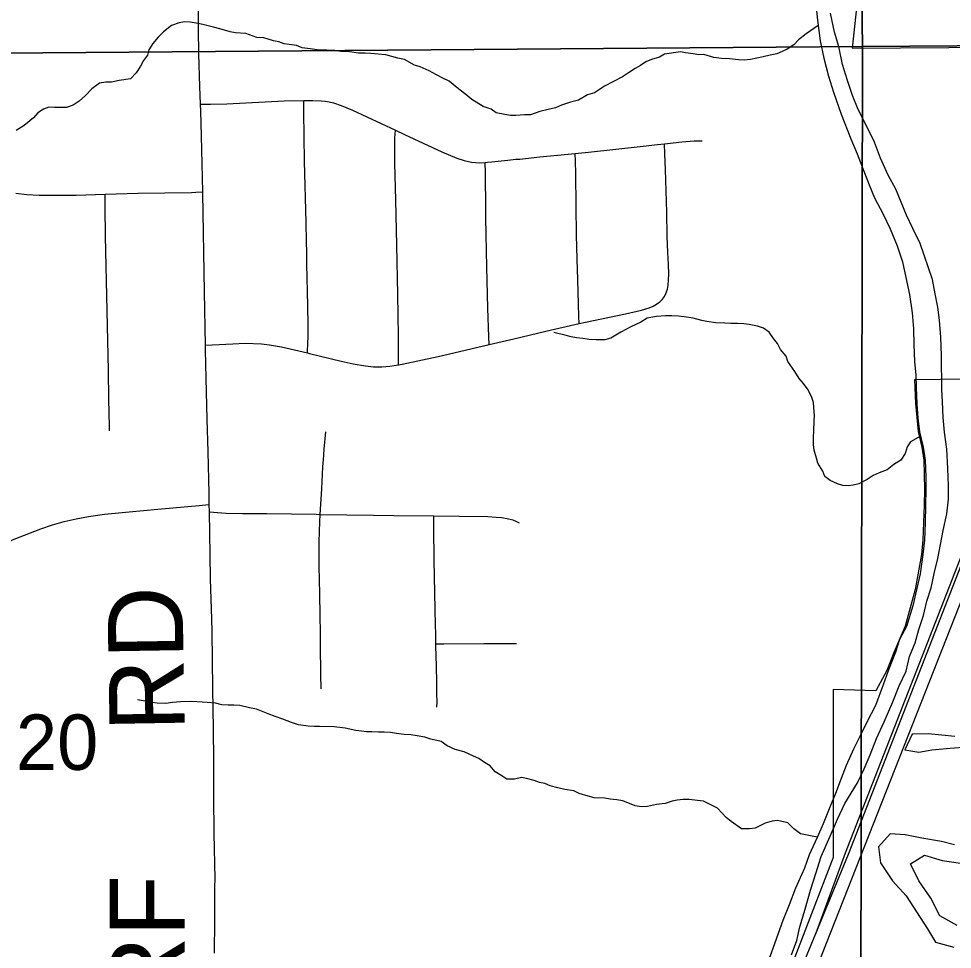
# Model space of a CAD drawing. Extents: x 0 to 34, y 0 to 22.
# Drawn here: x 7.158 to 7.864, y 18.2 to 18.904 of the extents above; entities that cross this region are included whole.
import ezdxf

# ---------------------------------------------------------------- set-up
doc = ezdxf.new("R2010")
doc.units = 0
for name, color, linetype in [('Default', 7, 'Continuous'), ('GM_X_Major_River', 7, 'Continuous'), ('GM_X_Minor_River', 7, 'Continuous'), ('GM_X_Rail_Line', 7, 'Continuous'), ('GM_X_Section', 7, 'Continuous'), ('GM_X_Section_Text', 7, 'Continuous'), ('GM_X_Township_Road', 7, 'Continuous'), ('GM_X_Township_Road_Text', 7, 'Continuous')]:
    doc.layers.add(name, color=color, linetype=linetype)

msp = doc.modelspace()

# ---------------------------------------------------------------- linework, layer by layer
at = {"layer": 'Default'}
for points in [[(7.81905, 19.16934), (7.78812, 18.88167), (7.97091, 18.88297)], [(7.87401, 18.63157), (7.83533, 18.63091), (7.83607, 18.61316), (7.83811, 18.59194), (7.84085, 18.5802), (7.84242, 18.57035), (7.84296, 18.54836), (7.84266, 18.53623), (7.84171, 18.51005), (7.84065, 18.49905), (7.83591, 18.47246), (7.82815, 18.44472), (7.81995, 18.42531), (7.81436, 18.41124), (7.80613, 18.39581), (7.77387, 18.39692), (7.77385, 18.26998), (7.71339, 18.11258)]]:
    msp.add_lwpolyline(points, dxfattribs=at)
at = {"layer": 'GM_X_Major_River'}
for points in [[(7.76077, 18.91468), (7.76199, 18.90293), (7.76399, 18.8874), (7.76673, 18.87415), (7.77024, 18.86052), (7.77411, 18.84841), (7.7799, 18.83177), (7.78723, 18.81324), (7.79185, 18.8019), (7.79571, 18.79207), (7.8011, 18.77846), (7.80496, 18.76862), (7.81148, 18.75616), (7.81686, 18.7452), (7.82225, 18.73235), (7.82612, 18.72024), (7.82885, 18.7085), (7.83159, 18.69563), (7.83358, 18.68161), (7.83442, 18.66948), (7.83488, 18.65773), (7.83535, 18.64484), (7.83618, 18.63461), (7.83662, 18.62513), (7.83709, 18.613), (7.83792, 18.602), (7.83913, 18.59178), (7.84186, 18.58004), (7.84344, 18.57019), (7.84391, 18.55768), (7.84397, 18.5482), (7.84368, 18.53606), (7.84339, 18.52316), (7.84272, 18.50989), (7.84166, 18.49888), (7.83949, 18.48445), (7.83692, 18.4723), (7.83398, 18.46014), (7.82916, 18.44455), (7.82392, 18.43465), (7.82096, 18.42515), (7.81538, 18.41107)], [(7.85685, 18.60253), (7.85639, 18.61428), (7.85595, 18.62376), (7.85577, 18.64954), (7.8553, 18.6632), (7.85407, 18.67608), (7.85287, 18.68593), (7.8509, 18.69615), (7.84894, 18.70676), (7.83966, 18.734), (7.8339, 18.74533), (7.82928, 18.75553), (7.8212, 18.77519), (7.81544, 18.78577), (7.80967, 18.79862), (7.80504, 18.81072), (7.79928, 18.82243), (7.79275, 18.83528), (7.78852, 18.84587), (7.78465, 18.85722), (7.78078, 18.86932), (7.77803, 18.88295), (7.77493, 18.89393), (7.7718, 18.90832)], [(7.74225, 18.19625), (7.74634, 18.20728), (7.74854, 18.21754), (7.75262, 18.23084), (7.75668, 18.24528), (7.76076, 18.25783), (7.76484, 18.27075), (7.77155, 18.28598), (7.77714, 18.29891), (7.78274, 18.31071), (7.7921, 18.32633), (7.79733, 18.33699), (7.8018, 18.34764), (7.80664, 18.35981), (7.81224, 18.37237), (7.81895, 18.38759), (7.82379, 18.39976), (7.82901, 18.4108), (7.83159, 18.42182), (7.83568, 18.43209), (7.83864, 18.44235), (7.84198, 18.45299), (7.84455, 18.46363), (7.84789, 18.47389), (7.85009, 18.48453), (7.85304, 18.49593), (7.85486, 18.50656), (7.85706, 18.5172), (7.85963, 18.52973), (7.86107, 18.54074), (7.86099, 18.55098), (7.86053, 18.56387), (7.85967, 18.57866), (7.85807, 18.59154), (7.85685, 18.60253)], [(7.81538, 18.41107), (7.81166, 18.40043), (7.80571, 18.38483), (7.79936, 18.37227), (7.79413, 18.36199), (7.78928, 18.35172), (7.78368, 18.33954), (7.77996, 18.32965), (7.77549, 18.31824), (7.7714, 18.30797), (7.76618, 18.29542), (7.76171, 18.28514), (7.75574, 18.27182), (7.75202, 18.26193), (7.74531, 18.24671), (7.74047, 18.23416), (7.73563, 18.22237), (7.73229, 18.21248), (7.7282, 18.20108), (7.72449, 18.19081)]]:
    msp.add_lwpolyline(points, dxfattribs=at)
at = {"layer": 'GM_X_Minor_River'}
for points in [[(7.7625, 18.89898), (7.75335, 18.8927), (7.7477, 18.88807), (7.74395, 18.88422), (7.73904, 18.88111), (7.73527, 18.87917), (7.7311, 18.87759), (7.72617, 18.87638), (7.72087, 18.87518), (7.71138, 18.87315), (7.70645, 18.8727), (7.70226, 18.87303), (7.6954, 18.87369), (7.68931, 18.87399), (7.6836, 18.87468), (7.67597, 18.87686), (7.67216, 18.8768), (7.66797, 18.87751), (7.66226, 18.87819), (7.65844, 18.8789), (7.6463, 18.87722), (7.64252, 18.87489), (7.63646, 18.87329), (7.6323, 18.87133), (7.62815, 18.86862), (7.624, 18.86628), (7.6191, 18.86318), (7.61457, 18.86008), (7.60097, 18.85306), (7.59343, 18.84803), (7.58813, 18.84643), (7.58133, 18.84254), (7.57527, 18.84095), (7.56845, 18.83857), (7.56391, 18.83661), (7.55822, 18.8354), (7.55216, 18.8338), (7.54496, 18.83143), (7.5404, 18.83136), (7.53394, 18.8309), (7.52976, 18.83084), (7.52557, 18.83155), (7.51908, 18.83298), (7.51524, 18.83559), (7.50913, 18.83778), (7.5007, 18.84299), (7.49608, 18.84673), (7.49185, 18.85009), (7.48801, 18.85308), (7.4834, 18.85681), (7.47881, 18.85903), (7.47383, 18.86162), (7.46847, 18.86459), (7.46158, 18.86754), (7.45738, 18.869), (7.44972, 18.87308), (7.44476, 18.87415), (7.4356, 18.87669), (7.42418, 18.87768), (7.41999, 18.878), (7.41505, 18.87793), (7.40819, 18.87898), (7.40172, 18.87928), (7.39715, 18.87998), (7.39106, 18.88027), (7.38383, 18.88056), (7.37849, 18.88125), (7.3724, 18.88193), (7.36819, 18.88377), (7.36248, 18.88445), (7.35867, 18.88516), (7.35484, 18.88663), (7.35065, 18.88733), (7.3434, 18.88951), (7.33807, 18.88982), (7.32967, 18.89275), (7.32205, 18.89341), (7.31786, 18.89411), (7.31022, 18.89629), (7.30526, 18.89774), (7.29725, 18.89953), (7.29229, 18.90061), (7.28772, 18.90131), (7.28353, 18.90163), (7.27936, 18.90082), (7.27368, 18.89884), (7.26765, 18.8942), (7.26352, 18.88997), (7.2594, 18.88535), (7.25642, 18.88038), (7.25533, 18.87656), (7.25234, 18.87235), (7.25012, 18.86814), (7.24676, 18.86315), (7.24263, 18.85854), (7.2339, 18.85728), (7.22821, 18.85607), (7.22403, 18.85601), (7.2191, 18.85519)], [(7.2191, 18.85519), (7.21345, 18.85093), (7.20857, 18.84593), (7.20368, 18.84169), (7.19916, 18.83859), (7.19423, 18.837), (7.18511, 18.83688), (7.18092, 18.83721), (7.17676, 18.83563), (7.17261, 18.83292), (7.16924, 18.82907), (7.16209, 18.82328), (7.15605, 18.8194)], [(7.83991, 18.58839), (7.83228, 18.58417), (7.82967, 18.58033), (7.82821, 18.57538), (7.82485, 18.57039), (7.81957, 18.5669), (7.81468, 18.56304), (7.80862, 18.56068), (7.80408, 18.55872), (7.79956, 18.55562), (7.79314, 18.5525), (7.78897, 18.5513), (7.78517, 18.55087), (7.78098, 18.55119), (7.77717, 18.55228), (7.77142, 18.55487), (7.76758, 18.55786), (7.76601, 18.56201), (7.76213, 18.56804), (7.76132, 18.57182), (7.75934, 18.57788), (7.7589, 18.58205), (7.75883, 18.58775), (7.75915, 18.59231), (7.75943, 18.59991), (7.75976, 18.60371), (7.7593, 18.61016), (7.75887, 18.61396), (7.75768, 18.61774), (7.75494, 18.6234), (7.75146, 18.62829), (7.74798, 18.63204), (7.74487, 18.63732), (7.73945, 18.64485), (7.73826, 18.64901), (7.73401, 18.65389), (7.73167, 18.65842), (7.72858, 18.66218), (7.72547, 18.66707), (7.72125, 18.67005), (7.71667, 18.67151), (7.71018, 18.67295), (7.70637, 18.67328), (7.70143, 18.67359), (7.69648, 18.67352), (7.69191, 18.67384), (7.68507, 18.67413), (7.67821, 18.67518), (7.67439, 18.67589), (7.6679, 18.6777), (7.66104, 18.67875), (7.65685, 18.67907), (7.65191, 18.67939), (7.64696, 18.67932), (7.64012, 18.67885), (7.63329, 18.67762), (7.62839, 18.67451), (7.62083, 18.671), (7.61328, 18.6671), (7.60573, 18.66244), (7.60118, 18.66124), (7.59471, 18.66115), (7.58939, 18.66146), (7.58443, 18.66215), (7.57986, 18.66285), (7.57567, 18.66356), (7.57185, 18.66464), (7.5627, 18.6668)], [(7.76182, 18.28538), (7.74903, 18.28791), (7.74404, 18.29164), (7.73942, 18.29614), (7.73179, 18.29793), (7.72761, 18.2975), (7.7223, 18.29591), (7.71475, 18.29201), (7.71057, 18.29157), (7.70449, 18.29149), (7.69681, 18.29709), (7.69297, 18.30007), (7.68641, 18.30721), (7.67569, 18.31238), (7.66464, 18.31375), (7.66046, 18.3137), (7.6559, 18.31326), (7.65211, 18.31245), (7.64681, 18.31086), (7.64035, 18.31001), (7.63353, 18.3084), (7.62896, 18.30834), (7.62401, 18.30903), (7.61483, 18.31271), (7.61026, 18.31341), (7.60531, 18.3141), (7.60112, 18.3148), (7.59313, 18.31508), (7.58855, 18.31616), (7.58167, 18.31834), (7.57785, 18.32019), (7.57099, 18.32124), (7.56564, 18.32269), (7.55992, 18.32413), (7.55571, 18.32597), (7.5519, 18.32668), (7.5477, 18.32815), (7.54197, 18.32959), (7.53816, 18.3303), (7.53285, 18.32909), (7.52715, 18.32901), (7.52331, 18.33162), (7.51833, 18.33459), (7.51447, 18.3391), (7.51025, 18.3417), (7.50603, 18.34468), (7.50182, 18.34653), (7.49493, 18.34985), (7.48806, 18.35166), (7.48194, 18.35424), (7.47734, 18.3576), (7.46971, 18.35939), (7.46512, 18.36085), (7.45941, 18.36192), (7.45445, 18.36261), (7.4495, 18.36292), (7.44379, 18.36361), (7.43922, 18.36431), (7.43427, 18.36462), (7.43009, 18.36457), (7.42514, 18.36488), (7.42096, 18.36482), (7.41714, 18.36553), (7.41296, 18.36586), (7.40495, 18.36765), (7.39657, 18.36868), (7.38553, 18.36891), (7.38135, 18.36885), (7.37678, 18.36917), (7.36954, 18.37021), (7.36419, 18.37204), (7.3577, 18.37461), (7.35197, 18.37644), (7.34661, 18.37864), (7.34164, 18.38048), (7.33782, 18.38195), (7.33249, 18.38301), (7.32524, 18.38482), (7.32067, 18.38514), (7.31649, 18.38508), (7.31153, 18.38539), (7.30696, 18.38647), (7.30048, 18.38714), (7.29668, 18.38747), (7.28907, 18.38775), (7.28032, 18.38764), (7.27424, 18.38718), (7.26931, 18.38635), (7.26284, 18.38664), (7.25598, 18.38769), (7.25217, 18.3884), (7.24797, 18.38911)], [(7.86571, 18.36139), (7.85586, 18.36246), (7.84563, 18.36352), (7.83351, 18.36305), (7.82791, 18.35125), (7.83853, 18.34943), (7.84836, 18.3514), (7.86236, 18.35265), (7.87561, 18.3535)], [(7.86552, 18.27948), (7.85565, 18.28206), (7.84087, 18.2846), (7.82835, 18.28716), (7.81699, 18.28783), (7.80796, 18.2779), (7.80956, 18.26578), (7.81874, 18.2522), (7.82905, 18.2409), (7.84513, 18.21599), (7.85126, 18.2058), (7.86492, 18.20211)], [(7.86746, 18.21843), (7.85453, 18.22592), (7.84762, 18.23914), (7.83844, 18.25235), (7.83229, 18.26519), (7.84285, 18.27172), (7.85613, 18.26765), (7.87547, 18.26476)]]:
    msp.add_lwpolyline(points, dxfattribs=at)
at = {"layer": 'GM_X_Rail_Line'}
for points in [[(7.41554, 16.97974), (7.45576, 17.1778), (7.51777, 17.49987), (7.54259, 17.62251), (7.57169, 17.70433), (7.63213, 17.85839), (7.88249, 18.49369), (8.02356, 18.85844), (8.15149, 19.17223), (8.16753, 19.23137), (8.32815, 19.89453)], [(7.19563, 16.97974), (7.27479, 17.11509), (7.3911, 17.31365), (7.42821, 17.37942), (7.44573, 17.41447), (7.46435, 17.45781), (7.63148, 17.88537), (7.72591, 18.12796), (7.78531, 18.27252), (7.87835, 18.51079), (8.16871, 19.24707)], [(7.76057, 18.21231), (7.78312, 18.27339), (7.87615, 18.51164), (8.16651, 19.24792)]]:
    msp.add_lwpolyline(points, dxfattribs=at)
at = {"layer": 'GM_X_Section'}
for points in [[(6.77985, 19.89133), (7.78202, 19.88507), (7.79585, 18.88307), (6.78469, 18.87524)], [(7.78202, 19.88507), (8.79094, 19.88871), (8.79603, 18.89006), (7.79585, 18.88307)], [(8.79603, 18.89006), (8.80273, 17.87625), (7.79423, 17.86732), (7.79585, 18.88307)], [(7.79585, 18.88307), (7.79423, 17.86732), (6.79787, 17.8558), (6.78469, 18.87524)]]:
    msp.add_lwpolyline(points, close=True, dxfattribs=at)
at = {"layer": 'GM_X_Township_Road'}
msp.add_line((7.30225, 18.53123), (7.30212, 18.53678), dxfattribs=at)
for points in [[(7.29554, 18.83938), (7.29506, 18.85276), (7.29435, 18.87755), (7.29408, 18.89617), (7.294, 18.91482), (7.29395, 18.92104), (7.29393, 18.92414), (7.29351, 18.9552), (7.29326, 18.97694), (7.29308, 18.9987), (7.29244, 19.05463), (7.29207, 19.08259), (7.29147, 19.11981), (7.29123, 19.13846), (7.29099, 19.1571), (7.29085, 19.17263), (7.2909, 19.19437), (7.29063, 19.21611), (7.29008, 19.26894), (7.289, 19.37152), (7.28896, 19.38257)], [(7.29554, 18.83938), (7.30311, 18.83953), (7.31544, 18.83977), (7.35869, 18.84186), (7.37364, 18.84214)], [(7.29722, 18.77303), (7.29626, 18.8156), (7.29574, 18.83418), (7.29554, 18.83938)], [(7.37364, 18.84214), (7.3804, 18.84227), (7.38667, 18.84203), (7.38979, 18.84168), (7.3929, 18.84113), (7.39596, 18.8404), (7.40193, 18.83844), (7.41054, 18.8348), (7.44283, 18.81967)], [(7.37635, 18.65139), (7.37668, 18.6594), (7.3768, 18.6625), (7.37685, 18.67177), (7.37655, 18.68723), (7.37596, 18.71846), (7.3758, 18.72753), (7.37567, 18.73525), (7.37542, 18.74989), (7.37408, 18.79623), (7.37372, 18.83357), (7.37364, 18.84214)], [(7.4453, 18.64246), (7.44527, 18.64857), (7.44519, 18.6644), (7.44468, 18.69547), (7.44396, 18.73276), (7.44308, 18.76693), (7.4425, 18.79489), (7.44232, 18.80447), (7.44232, 18.80793), (7.44235, 18.81368), (7.44283, 18.81967)], [(7.44283, 18.81967), (7.4498, 18.8164), (7.47794, 18.80341), (7.48927, 18.79856), (7.49496, 18.79677), (7.50046, 18.79563), (7.50344, 18.79529), (7.50649, 18.79515), (7.51082, 18.79538)], [(7.64636, 18.8095), (7.65946, 18.81094), (7.66869, 18.81169), (7.67178, 18.81176), (7.67481, 18.81166)], [(7.57883, 18.80224), (7.58887, 18.80325), (7.63023, 18.80774)], [(7.63023, 18.80774), (7.64106, 18.80892), (7.64636, 18.8095)], [(7.64633, 18.69403), (7.64765, 18.69682), (7.64856, 18.69949), (7.64908, 18.70256), (7.6494, 18.70664), (7.64948, 18.71097), (7.64933, 18.7181), (7.64887, 18.72736), (7.64838, 18.73976), (7.64806, 18.75789), (7.64692, 18.78997), (7.6465, 18.80191), (7.64636, 18.8095)], [(7.51082, 18.79538), (7.51251, 18.79546), (7.51555, 18.79579), (7.52776, 18.7971), (7.53389, 18.79788), (7.53684, 18.79797), (7.55204, 18.79956), (7.57883, 18.80224)], [(7.58179, 18.67353), (7.58163, 18.67908), (7.58138, 18.68817), (7.58086, 18.70681), (7.58014, 18.72223), (7.5798, 18.74074), (7.5795, 18.76232), (7.57923, 18.78694), (7.57899, 18.79615), (7.57883, 18.80224)], [(7.51379, 18.65771), (7.51359, 18.66352), (7.51283, 18.68518), (7.51205, 18.7162), (7.51118, 18.75347), (7.5111, 18.7659), (7.51095, 18.78127), (7.51089, 18.78763), (7.51082, 18.79538)], [(7.15589, 18.77208), (7.16421, 18.77104), (7.17354, 18.77068), (7.20157, 18.77072), (7.22339, 18.77136)], [(7.22339, 18.77136), (7.24829, 18.77208), (7.28878, 18.77272), (7.2919, 18.77283), (7.29722, 18.77303)], [(7.22681, 18.59244), (7.22673, 18.59582), (7.22625, 18.61653), (7.22584, 18.63808), (7.22499, 18.68324), (7.22365, 18.7396), (7.22347, 18.76152), (7.22339, 18.77136)], [(7.29928, 18.65736), (7.29848, 18.69755), (7.29724, 18.77214), (7.29722, 18.77303)], [(7.58179, 18.67353), (7.58664, 18.67463), (7.61688, 18.68098), (7.62891, 18.68367), (7.63481, 18.68542), (7.63764, 18.68661), (7.64033, 18.68812), (7.64279, 18.68996), (7.64485, 18.69206), (7.64633, 18.69403)], [(7.51379, 18.65771), (7.53245, 18.66211), (7.55653, 18.66777), (7.58179, 18.67353)], [(7.29928, 18.65736), (7.3044, 18.65759), (7.31987, 18.65827), (7.32915, 18.65868), (7.34152, 18.65835), (7.34766, 18.65759), (7.3568, 18.65592), (7.37635, 18.65139)], [(7.30212, 18.53678), (7.30194, 18.5454), (7.3012, 18.57647), (7.30051, 18.60128), (7.29978, 18.63232), (7.29936, 18.65354), (7.29928, 18.65736)], [(7.4453, 18.64246), (7.4479, 18.64289), (7.47513, 18.64879), (7.50834, 18.65642), (7.51379, 18.65771)], [(7.37635, 18.65139), (7.37793, 18.65103), (7.40197, 18.64509), (7.41103, 18.6431), (7.4202, 18.64158), (7.42635, 18.64093), (7.43254, 18.64085), (7.43871, 18.6414), (7.4453, 18.64246)], [(7.38594, 18.52932), (7.38715, 18.54856), (7.388, 18.5652), (7.38841, 18.57047), (7.38904, 18.57867), (7.39027, 18.59182)], [(7.12418, 18.49785), (7.12862, 18.49972), (7.12999, 18.50028), (7.15452, 18.51045), (7.17479, 18.51841), (7.18361, 18.52137), (7.19255, 18.52395), (7.2016, 18.52606), (7.21075, 18.52769), (7.22305, 18.52939), (7.24163, 18.53124), (7.26336, 18.53318), (7.29438, 18.53606), (7.30212, 18.53678)], [(7.30547, 18.34957), (7.3054, 18.36078), (7.30535, 18.36698), (7.30518, 18.38238), (7.30492, 18.39765), (7.3045, 18.41909), (7.30424, 18.44082), (7.30402, 18.45011), (7.30319, 18.48056), (7.30291, 18.49906), (7.30225, 18.53123)], [(7.30225, 18.53123), (7.30841, 18.53079), (7.31492, 18.53031), (7.32721, 18.52995), (7.34576, 18.52995), (7.38293, 18.52937), (7.38594, 18.52932)], [(7.38669, 18.39747), (7.38655, 18.40816), (7.38645, 18.41539), (7.38635, 18.42328), (7.38623, 18.432), (7.38614, 18.43925), (7.38595, 18.45328), (7.38573, 18.46878), (7.3855, 18.48021), (7.38523, 18.48952), (7.38523, 18.49565), (7.38523, 18.50239), (7.38523, 18.50858), (7.38561, 18.52378), (7.38594, 18.52932)], [(7.38594, 18.52932), (7.42627, 18.52861), (7.44173, 18.52839), (7.47182, 18.52814)], [(7.47342, 18.43132), (7.47332, 18.43925), (7.47315, 18.4454), (7.47214, 18.49463), (7.47181, 18.51925), (7.47181, 18.52286), (7.47182, 18.52814)], [(7.47182, 18.52814), (7.49114, 18.52798), (7.51284, 18.52767), (7.51905, 18.52727), (7.52312, 18.52693), (7.52746, 18.52613), (7.53154, 18.52508), (7.5343, 18.52402), (7.53629, 18.52286)], [(7.47342, 18.43132), (7.47944, 18.43137), (7.50975, 18.43163), (7.52188, 18.43171), (7.52951, 18.43165), (7.53445, 18.43161)], [(7.47425, 18.3836), (7.4743, 18.38722), (7.47429, 18.39397), (7.47427, 18.40232), (7.47386, 18.41462), (7.47344, 18.43001), (7.47342, 18.43132)], [(7.30619, 18.19771), (7.30629, 18.22238), (7.30634, 18.23373), (7.30636, 18.24064), (7.30639, 18.24764), (7.30647, 18.25383), (7.30588, 18.28803), (7.30568, 18.316), (7.30571, 18.32224), (7.30562, 18.32409), (7.30547, 18.34957)]]:
    msp.add_lwpolyline(points, dxfattribs=at)

# ---------------------------------------------------------------- texts
at = {"layer": 'GM_X_Section_Text'}
msp.add_text('20', height=0.041856, rotation=0.00001, dxfattribs=at).set_placement((7.15596, 18.33617))
at = {"layer": 'GM_X_Township_Road_Text'}
for s, rotation, p in [('RD', 90.95273, (7.28362, 18.36561)), ('BATDORF', 90, (7.2836, 17.89361))]:
    msp.add_text(s, height=0.056818, rotation=rotation, dxfattribs=at).set_placement(p)

doc.saveas('drawing.dxf')
